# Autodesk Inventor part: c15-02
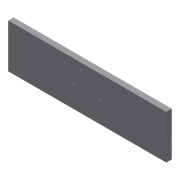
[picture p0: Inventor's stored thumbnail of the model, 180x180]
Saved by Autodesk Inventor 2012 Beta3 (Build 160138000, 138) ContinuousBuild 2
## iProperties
Created: 2011-02
Part Number: c15-02
Material: Default
Document SubType Name: Modeling
Designer: Beta-8540w
Density: 1 g/cm^3
Author: Beta-8540w
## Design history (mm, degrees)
sketch "Sketch1"
  geometry: L1 (-228.6, -63.5)-(228.6, -63.5); L2 (228.6, -63.5)-(228.6, 63.5); L3 (228.6, 63.5)-(-228.6, 63.5); L4 (-228.6, 63.5)-(-228.6, -63.5); 3 further points
  constraints: 8 end point, 2 midpoint, 2 parallel, 1 horizontal, 1 horizontal alignment, 1 perpendicular, 1 vertical alignment
  dimensions: "d0" = 457.2 distance of L3.end L2.end; "d1" = 127 distance of L2.end L1.end
extrude "Drawer Face" new body sketch "Sketch1" distance "d2" = 15.875; taper "d3" = 0 deg
sketch "Sketch2"
  geometry: 1 further point
hole "Single Hole Pull" sketch "Sketch2" at (0, 0) diameter "d4" = 4.4958; stored, may be unused: countersink angle "d8" = 82 deg, drill point angle "d10" = 118 deg; dims "d5" = 19.05, "d9" = 25.4, "d72" = 8.4328, "d73" = 6.35
sketch "Sketch3"
  geometry: L1 (-38.1, 0)-(38.1, 0); 2 further points
  constraints: 2 end point, 1 coincident, 1 horizontal, 1 midpoint
  dimensions: "d6" = 76.2 distance of L1.start L1.end
hole "Double Hole Pull" sketch "Sketch3" at (-38.1, 0), (38.1, 0) diameter "d7" = 4.4958; stored, may be unused: countersink angle "d16" = 82 deg, drill point angle "d18" = 118 deg; dims "d13" = 19.05, "d14" = 8.4328, "d15" = 6.35, "d17" = 25.4
body "Solid1"
